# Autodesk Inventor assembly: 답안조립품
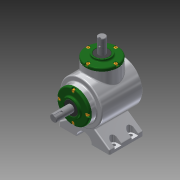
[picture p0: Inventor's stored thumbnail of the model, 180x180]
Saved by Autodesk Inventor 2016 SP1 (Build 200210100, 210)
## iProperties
Created: 2017-04
Part Number: 답안조립품
Material: 일반
Document SubType Name: Assembly
Designer: H
Author: H
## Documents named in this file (14)
- C:\Users\CAMTIC\Desktop\470407V1033\답안조립품.iam
- C:\Users\CAMTIC\Desktop\470407V1033\1-본체.ipt
- C:\Users\CAMTIC\Desktop\470407V1033\메인 베벨기어.ipt
- C:\Users\CAMTIC\Desktop\470407V1033\메인 축.ipt
- 메인 축.ipt
- C:\Users\CAMTIC\Desktop\470407V1033\베어링 6203.ipt
- C:\Users\CAMTIC\Desktop\470407V1033\볼트 M4.ipt
- C:\Users\CAMTIC\Desktop\470407V1033\서브 베벨기어.ipt
- C:\Users\CAMTIC\Desktop\470407V1033\서브 축.ipt
- 서브 축.ipt
- C:\Users\CAMTIC\Desktop\470407V1033\오일실 17 32 8.ipt
- C:\Users\CAMTIC\Desktop\470407V1033\커버.ipt
- C:\Users\CAMTIC\Desktop\470407V1033\키 4x4.ipt
- C:\Users\CAMTIC\Desktop\470407V1033\키 5x5.ipt
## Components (1 placed, 1 different names)
1. 1-본체:1
